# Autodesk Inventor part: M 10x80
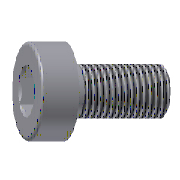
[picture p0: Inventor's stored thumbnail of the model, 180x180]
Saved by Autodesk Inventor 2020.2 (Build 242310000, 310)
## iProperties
Manager: www.cadconsulting.pl
Company: Fabian Stasiak CAD Consulting
Created: 2014-02
Part Number: M 10x80
Material: Stal, miękka
Description: Socket Head Cap Screw DIN 912 - 12.9
Document SubType Name: Modeling
Designer: F.Stasiak
Standard Revision: 1
Manufacturer: DME
Language: pl-PL
Size Designation: 10x80
Categories: <MemberInstance><Categories><Category DisplayName="Forma wtryskowa" InternalName="349578f2-f4d4-4954-8c09-8e99297a61c0" Mnemonic="MOLD"><Category DisplayName="C
Mass: 0.133121 g
Surface Area: 2.01441 cm^2
Volume: 0.133121 cm^3
Density: 7.85 g/cm^3
Appearance: Częściowo polerowana
Catalog Web Link: www.expertbooks.pl
IsCustomPart: 0
Author: F.Stasiak
Subject: Zbiór ćwiczeń. Autodesk Inventor 2020. Kurs Professional
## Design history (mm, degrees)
sketch "Sketch1"
  geometry: L1 (0, -98)-(0, 28) reference; L2 (4.619, 10)-(8, 10); L3 (8, 10)-(8, 0); L4 (8, 0)-(5, 0); L5 (5, 0)-(5, -80); L6 (5, -80)-(0, -80); L7 (0, 2.597)-(0, -80); L8 (0, 2.597)-(4, 5); L9 (4, 5)-(4, 9.381); L10 (4, 9.381)-(4.619, 10); 1 further point
  constraints: 18 end point, 4 vertical, 3 horizontal, 2 point on line
  dimensions: "d0" = 16 diameter of L3 L1 (= dk); "d1" = 10 distance between parallel lines of L4 L2 (= k); "d2" = 10 diameter of L5 L1 (= d); "d3" = 80 distance between parallel lines of L6 L4 (= L); "d4" = 59 deg angle of L1 L8; "d5" = 45 deg angle of L1 L10; "d6" = 8 diameter of L9 L1 (= sw); "d7" = 9.2376 diameter of L2.start L1 (= 1.1547 x sw); "d8" = 5 distance from line of L8.end L2 (= t)
revolve "Revolution1" sketch "Sketch1" stored, may be unused: angle "d44" = 90 deg
sketch "Sketch2"
  geometry: L1 (0, 4.619)-(4, 2.309); L2 (4, 2.309)-(4, -2.309); L3 (4, -2.309)-(0, -4.619); L4 (0, -4.619)-(-4, -2.309); L5 (-4, -2.309)-(-4, 2.309); L6 (-4, 2.309)-(0, 4.619); 3 further points
  constraints: 12 end point, 2 vertical alignment, 1 coincident, 14 other
extrude "Extrusion1" cut sketch "Sketch2" taper "d9" = 0 deg; stored distance "d45" = 10
thread "Thread1" dims "d10" = 25 (= b), "d11" = 0
chamfer "Chamfer1" distance "d12" = 0.75 (= 0.5 x P); stored, may be unused: second distance "d50" = 2, angle "d51" = 45 deg
fillet "Fillet1" dims "d13" = 0.75 (= 0.5 x P)
body "Solid1"
other parameters: "d" = 10 [user parameter; used in 1 equation term], "L" = 80 [user parameter; used in 1 equation term], "dk" = 16 [user parameter; used in 1 equation term], "b" = 25 [user parameter; used in 1 equation term], "k" = 10 [user parameter; used in 1 equation term], "sw" = 8 [user parameter; used in 2 equation terms], "t" = 5 [user parameter; used in 1 equation term], "P" = 1.5 [user parameter; used in 2 equation terms], "d14" = 0, "d15" = 0, "d55" = 0
